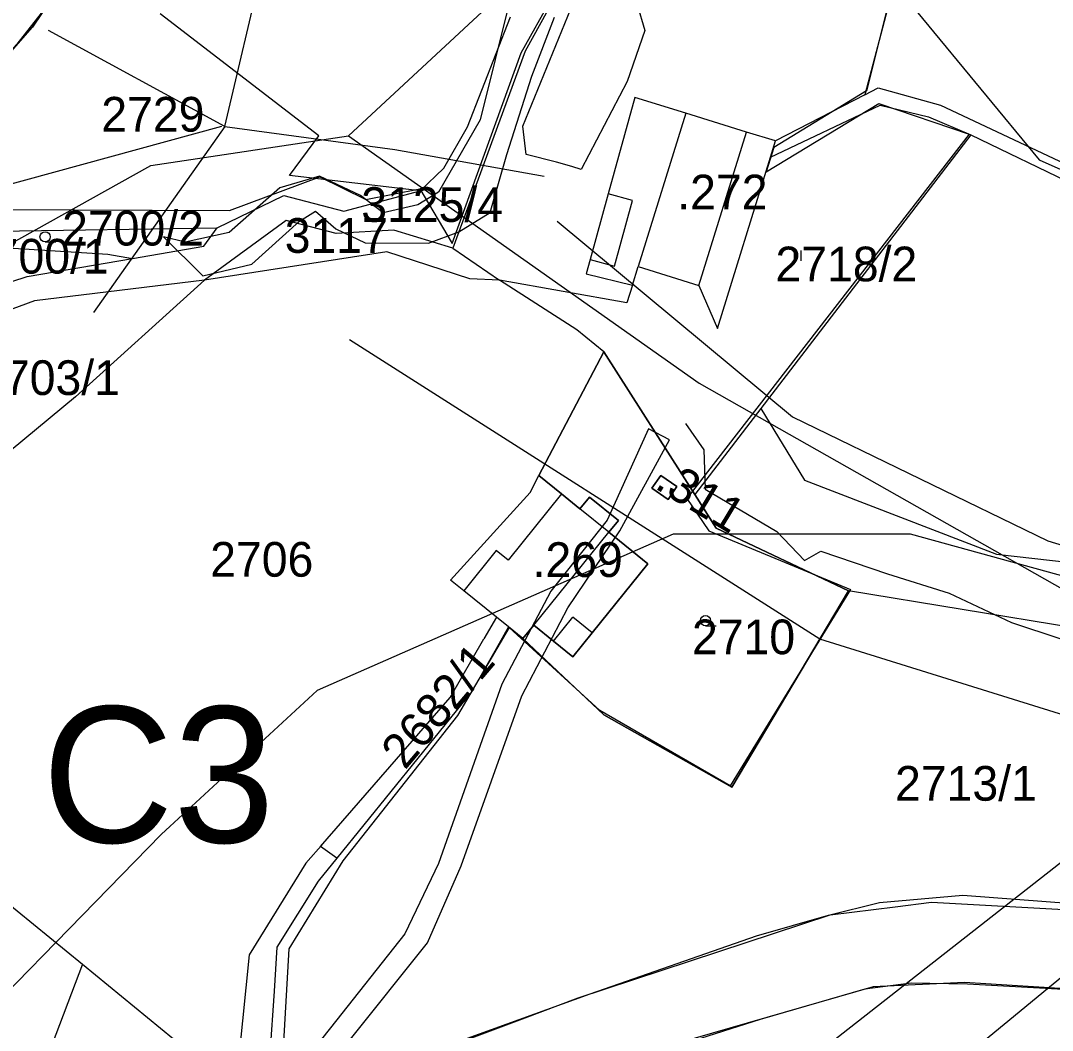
# Model space of a CAD drawing. Extents: x -564810 to -550519, y -1045831 to -1034011.
# Drawn here: x -552426.8 to -552275.1, y -1036269 to -1036120.6 of the extents above; entities that cross this region are included whole.
import ezdxf

# ---------------------------------------------------------------- set-up
doc = ezdxf.new("R2010")
doc.units = 0
for name, color, linetype in [('KN stav', 7, 'Continuous'), ('Obvod KPU', 7, 'Continuous'), ('Odvodněné plochy', 7, 'Continuous'), ('označ pol cest', 7, 'Continuous'), ('Parcelní čísla', 7, 'Continuous'), ('Polní cesty stavající', 7, 'Continuous'), ('STG', 7, 'Continuous'), ('Vedení VN', 7, 'Continuous'), ('vodní toky', 7, 'Continuous'), ('Vrstva 18', 7, 'Continuous'), ('Vrstva 22', 7, 'Continuous'), ('Vrstva 33', 7, 'Continuous'), ('Vrstva 39', 7, 'Continuous'), ('Vrstva 4', 7, 'Continuous'), ('zamokř ploch', 7, 'Continuous')]:
    doc.layers.add(name, color=color, linetype=linetype)

msp = doc.modelspace()

# ---------------------------------------------------------------- linework, layer by layer
at = {"layer": 'KN stav'}
for p, q in [((-552397.46, -1036080.72), (-552425.11, -1036121.49)), ((-552295.16, -1036103.15), (-552302.65, -1036131.45)), ((-552341.89, -1036105.59), (-552352.64, -1036125.03)), ((-552382.96, -1036137.48), (-552406.3, -1036119.56)), ((-552361.09, -1036136.19), (-552354.77, -1036120.01)), ((-552425.11, -1036121.49), (-552447.79, -1036146.11)), ((-552352.64, -1036125.03), (-552363.28, -1036153.98)), ((-552302.65, -1036131.45), (-552300.67, -1036130.43)), ((-552300.67, -1036130.43), (-552291.53, -1036132.98)), ((-552336.5, -1036131.84), (-552340.4, -1036146)), ((-552328.98, -1036134.18), (-552336.5, -1036131.84)), ((-552302.65, -1036131.45), (-552315.78, -1036138.2)), ((-552320.04, -1036136.96), (-552328.98, -1036134.18)), ((-552316.54, -1036140.64), (-552300.39, -1036132.96)), ((-552300.39, -1036132.96), (-552293.28, -1036134.71)), ((-552291.53, -1036132.98), (-552235.54, -1036159.29)), ((-552293.28, -1036134.71), (-552287.04, -1036137.32)), ((-552387.29, -1036143.3), (-552382.96, -1036137.48)), ((-552364.57, -1036142.26), (-552361.09, -1036136.19)), ((-552315.78, -1036138.2), (-552320.04, -1036136.96)), ((-552287.04, -1036137.32), (-552317.96, -1036177.57)), ((-552287.04, -1036137.32), (-552237.04, -1036161.54)), ((-552316.54, -1036140.64), (-552315.78, -1036138.2)), ((-552324.33, -1036165.79), (-552316.54, -1036140.64)), ((-552368.06, -1036145.56), (-552387.29, -1036143.3)), ((-552368.06, -1036145.56), (-552364.57, -1036142.26)), ((-552397.93, -1036151.01), (-552388.1, -1036146.28)), ((-552388.1, -1036146.28), (-552379.31, -1036148.58)), ((-552379.31, -1036148.58), (-552368.06, -1036145.56)), ((-552340.4, -1036146), (-552343.06, -1036155.67)), ((-552431.25, -1036151.53), (-552397.93, -1036151.01)), ((-552399.89, -1036153.71), (-552397.93, -1036151.01)), ((-552387.77, -1036149.95), (-552399.79, -1036158.73)), ((-552380.44, -1036151.87), (-552387.77, -1036149.95)), ((-552371.94, -1036151.38), (-552380.44, -1036151.87)), ((-552363.28, -1036153.98), (-552371.94, -1036151.38)), ((-552435.51, -1036153.55), (-552414.02, -1036154.88)), ((-552410.39, -1036155.51), (-552399.89, -1036153.71)), ((-552363.28, -1036153.98), (-552356.41, -1036158.73)), ((-552425.89, -1036158.17), (-552410.39, -1036155.51)), ((-552414.02, -1036154.88), (-552410.39, -1036155.51)), ((-552372.96, -1036154.52), (-552399.79, -1036158.73)), ((-552360.75, -1036158.49), (-552372.96, -1036154.52)), ((-552343.06, -1036155.67), (-552343.64, -1036157.77)), ((-552336.84, -1036159.44), (-552335.99, -1036156.71)), ((-552335.99, -1036156.71), (-552327.05, -1036159.49)), ((-552431.96, -1036160.17), (-552425.89, -1036158.17)), ((-552399.79, -1036158.73), (-552424.82, -1036161.75)), ((-552399.79, -1036158.73), (-552418.79, -1036175.85)), ((-552356.41, -1036158.73), (-552360.75, -1036158.49)), ((-552337.65, -1036162.06), (-552356.41, -1036158.73)), ((-552345.01, -1036166.01), (-552356.41, -1036158.73)), ((-552343.64, -1036157.77), (-552336.84, -1036159.44)), ((-552336.84, -1036159.44), (-552337.65, -1036162.06)), ((-552327.05, -1036159.49), (-552324.33, -1036165.79)), ((-552424.82, -1036161.75), (-552431.48, -1036164.21)), ((-552341.03, -1036169.22), (-552345.01, -1036166.01)), ((-552350.59, -1036187.42), (-552341.03, -1036169.22)), ((-552341.03, -1036169.22), (-552350.59, -1036187.42)), ((-552327.68, -1036190.21), (-552341.03, -1036169.22)), ((-552341.03, -1036169.22), (-552327.68, -1036190.21)), ((-552418.79, -1036175.85), (-552438.69, -1036192.39)), ((-552317.96, -1036177.57), (-552327.68, -1036190.21)), ((-552317.96, -1036177.57), (-552311.51, -1036188.1)), ((-552351.9, -1036189.91), (-552350.59, -1036187.42)), ((-552350.59, -1036187.42), (-552347.26, -1036190.12)), ((-552347.26, -1036190.12), (-552350.59, -1036187.42)), ((-552332.68, -1036187.42), (-552333.97, -1036189.3)), ((-552333.97, -1036189.3), (-552332.68, -1036187.42)), ((-552330.29, -1036189.06), (-552332.68, -1036187.42)), ((-552332.68, -1036187.42), (-552330.29, -1036189.06)), ((-552331.58, -1036190.94), (-552330.29, -1036189.06)), ((-552330.29, -1036189.06), (-552331.58, -1036190.94)), ((-552311.51, -1036188.1), (-552283.29, -1036198.98)), ((-552363.6, -1036202.79), (-552351.9, -1036189.91)), ((-552347.26, -1036190.12), (-552344.56, -1036192.3)), ((-552344.56, -1036192.3), (-552347.26, -1036190.12)), ((-552344.56, -1036192.3), (-552343.17, -1036190.59)), ((-552343.17, -1036190.59), (-552344.56, -1036192.3)), ((-552343.17, -1036190.59), (-552338.91, -1036194.04)), ((-552338.91, -1036194.04), (-552343.17, -1036190.59)), ((-552333.97, -1036189.3), (-552331.58, -1036190.94)), ((-552331.58, -1036190.94), (-552333.97, -1036189.3)), ((-552327.68, -1036190.21), (-552324.54, -1036195.15)), ((-552324.54, -1036195.15), (-552327.68, -1036190.21)), ((-552338.91, -1036194.04), (-552340.3, -1036195.75)), ((-552340.3, -1036195.75), (-552338.91, -1036194.04)), ((-552324.54, -1036195.15), (-552305.05, -1036204.4)), ((-552305.05, -1036204.4), (-552324.54, -1036195.15)), ((-552340.3, -1036195.75), (-552334.57, -1036200.39)), ((-552334.57, -1036200.39), (-552340.3, -1036195.75)), ((-552283.29, -1036198.98), (-552272.45, -1036200.19)), ((-552334.57, -1036200.39), (-552342.78, -1036210.54)), ((-552342.78, -1036210.54), (-552334.57, -1036200.39)), ((-552361.65, -1036204.37), (-552363.6, -1036202.79)), ((-552356.83, -1036208.27), (-552361.65, -1036204.37)), ((-552305.05, -1036204.4), (-552322.21, -1036233.22)), ((-552322.21, -1036233.22), (-552305.05, -1036204.4)), ((-552269.02, -1036210.3), (-552305.05, -1036204.4)), ((-552356.83, -1036208.27), (-552358.68, -1036211.46)), ((-552355.08, -1036209.69), (-552356.83, -1036208.27)), ((-552355.08, -1036209.69), (-552356.89, -1036212.89)), ((-552352.96, -1036211.4), (-552355.08, -1036209.69)), ((-552351.36, -1036209.43), (-552352.96, -1036211.4)), ((-552352.96, -1036211.4), (-552351.36, -1036209.43)), ((-552348.45, -1036211.78), (-552351.36, -1036209.43)), ((-552351.36, -1036209.43), (-552348.45, -1036211.78)), ((-552363.67, -1036220.06), (-552358.68, -1036211.46)), ((-552341.05, -1036222.63), (-552352.96, -1036211.4)), ((-552352.96, -1036211.4), (-552341.05, -1036222.63)), ((-552345.63, -1036214.06), (-552348.45, -1036211.78)), ((-552348.45, -1036211.78), (-552345.63, -1036214.06)), ((-552342.78, -1036210.54), (-552345.63, -1036214.06)), ((-552345.63, -1036214.06), (-552342.78, -1036210.54)), ((-552356.89, -1036212.89), (-552360.45, -1036219.2)), ((-552360.45, -1036219.2), (-552380.31, -1036243.66)), ((-552382.75, -1036241.98), (-552363.67, -1036220.06)), ((-552322.21, -1036233.22), (-552341.05, -1036222.63)), ((-552341.05, -1036222.63), (-552322.21, -1036233.22)), ((-552380.31, -1036243.66), (-552382.75, -1036241.98)), ((-552380.31, -1036243.66), (-552383.08, -1036247.07)), ((-552383.08, -1036247.07), (-552389.13, -1036256.75)), ((-552429.76, -1036249.45), (-552417.73, -1036259.25)), ((-552307.76, -1036252.02), (-552298.21, -1036250.82)), ((-552298.21, -1036250.82), (-552292.87, -1036250.15)), ((-552292.87, -1036250.15), (-552242.63, -1036252.92)), ((-552344.82, -1036264.22), (-552307.76, -1036252.02)), ((-552389.13, -1036256.75), (-552389.56, -1036263.25)), ((-552417.73, -1036259.25), (-552428.13, -1036286.71)), ((-552417.73, -1036259.25), (-552404.37, -1036270.22)), ((-552389.56, -1036263.25), (-552390.76, -1036281.4)), ((-552301.41, -1036262.6), (-552343.81, -1036274.77)), ((-552287.97, -1036261.97), (-552301.41, -1036262.6)), ((-552266.12, -1036263.35), (-552287.97, -1036261.97)), ((-552353.02, -1036267.28), (-552344.82, -1036264.22)), ((-552390.76, -1036281.4), (-552353.02, -1036267.28))]:
    msp.add_line(p, q, dxfattribs=at)
at = {"layer": 'Obvod KPU'}
for p, q in [((-552353.2, -1036125.31), (-552330.41, -1036084.2)), ((-552295.41, -1036102.94), (-552302.4, -1036130.89)), ((-552363.38, -1036153.34), (-552353.2, -1036125.31)), ((-552302.4, -1036130.89), (-552316.06, -1036139.19)), ((-552317.17, -1036142.76), (-552300.59, -1036132.72)), ((-552300.59, -1036132.72), (-552287.33, -1036137.23)), ((-552287.33, -1036137.23), (-552328.85, -1036190.79)), ((-552316.06, -1036139.19), (-552317.17, -1036142.76)), ((-552396.09, -1036148.48), (-552382.84, -1036143.54)), ((-552382.84, -1036143.54), (-552376.04, -1036146.85)), ((-552376.04, -1036146.85), (-552368.13, -1036145.3)), ((-552368.13, -1036145.3), (-552363.38, -1036153.34)), ((-552431.9, -1036148.29), (-552396.09, -1036148.48)), ((-552328.85, -1036190.79), (-552325.6, -1036195.54)), ((-552325.6, -1036195.54), (-552304.75, -1036204.17)), ((-552304.75, -1036204.17), (-552322.47, -1036233.03)), ((-552354.97, -1036209.79), (-552362.57, -1036222.7)), ((-552341.66, -1036221.97), (-552354.97, -1036209.79)), ((-552322.47, -1036233.03), (-552341.66, -1036221.97)), ((-552362.57, -1036222.7), (-552379.46, -1036244.05)), ((-552379.46, -1036244.05), (-552387.38, -1036256.99)), ((-552387.38, -1036256.99), (-552388.68, -1036279.64))]:
    msp.add_line(p, q, dxfattribs=at)
at = {"layer": 'Odvodněné plochy'}
msp.add_lwpolyline([(-552472.42, -1036175.42), (-552425.11, -1036121.49), (-552397.46, -1036080.72)], dxfattribs=at)
at = {"layer": 'Polní cesty stavající'}
for p, q in [((-552431.52, -1036129.27), (-552418.1, -1036112.21)), ((-552334.49, -1036180.54), (-552340.54, -1036193.98)), ((-552331.41, -1036182.16), (-552334.49, -1036180.54)), ((-552338.7, -1036195.56), (-552331.41, -1036182.16)), ((-552340.54, -1036193.98), (-552348.84, -1036204.41)), ((-552346.33, -1036206.87), (-552338.7, -1036195.56)), ((-552348.84, -1036204.41), (-552356.07, -1036218.1)), ((-552353.13, -1036219.82), (-552346.33, -1036206.87)), ((-552356.07, -1036218.1), (-552365.38, -1036244.47)), ((-552362.01, -1036244.82), (-552353.13, -1036219.82)), ((-552365.38, -1036244.47), (-552370.33, -1036254.79)), ((-552366.99, -1036256.14), (-552362.01, -1036244.82)), ((-552370.33, -1036254.79), (-552381.27, -1036268.6)), ((-552378.51, -1036270.51), (-552366.99, -1036256.14)), ((-552381.27, -1036268.6), (-552390.78, -1036280.68))]:
    msp.add_line(p, q, dxfattribs=at)
at = {"layer": 'STG'}
for points in [[(-552302.75, -1036109.8), (-552277.03, -1036141.04), (-552210.9, -1036170.44), (-552159.46, -1036194.33), (-552104.35, -1036229.24), (-552049.23, -1036221.89), (-551997.79, -1036236.59)], [(-551983.65, -1036332.97), (-552007.53, -1036309.09), (-552044.27, -1036295.3), (-552069.07, -1036358.7), (-552091.12, -1036381.67), (-552122.35, -1036426.69), (-552140.72, -1036452.42), (-552162.77, -1036443.23), (-552167.36, -1036398.21), (-552154.5, -1036338.49), (-552139.8, -1036286.12), (-552154.5, -1036260.39), (-552205.02, -1036223.64), (-552249.11, -1036208.94), (-552295.96, -1036196.07), (-552330.86, -1036196.07), (-552383.22, -1036219.04), (-552406.18, -1036240.18), (-552442.92, -1036277.85)]]:
    msp.add_lwpolyline(points, dxfattribs=at)
at = {"layer": 'Vedení VN'}
for p, q in [((-552396.81, -1036136.11), (-552422.74, -1036122.01)), ((-552397.31, -1036136.11), (-552443.59, -1036148.81)), ((-552396.81, -1036136.11), (-552416.11, -1036163.46))]:
    msp.add_line(p, q, dxfattribs=at)
for points in [[(-552390.69, -1036335.75), (-552182.99, -1036173.21), (-551916.64, -1036001.49), (-551790.75, -1035795.43)], [(-552393.68, -1036360.17), (-552349.55, -1036323.51), (-552259.68, -1036249.59), (-552179.99, -1036184.84), (-552081.56, -1036122.39), (-551986.35, -1036061.29), (-551910.18, -1036013.26), (-551850.19, -1035917.91), (-551788.14, -1035819.06)], [(-552396.81, -1036136.11), (-552385.51, -1036088.23), (-552374.49, -1036041.88), (-552363.46, -1035994.93), (-552350.12, -1035938.33)], [(-552396.81, -1036136.11), (-552371.78, -1036139.49), (-552349.84, -1036143.4)]]:
    msp.add_lwpolyline(points, dxfattribs=at)
at = {"layer": 'vodní toky'}
for p, q in [((-552354.85, -1036117.34), (-552359.25, -1036135.15)), ((-552352.95, -1036136.06), (-552345.92, -1036118.83)), ((-552336.12, -1036118.16), (-552335.04, -1036122.01)), ((-552351.66, -1036128.7), (-552348.29, -1036120.02)), ((-552335.04, -1036122.01), (-552337.6, -1036129.52)), ((-552355.3, -1036140.22), (-552351.66, -1036128.7)), ((-552337.6, -1036129.52), (-552344.37, -1036142.45)), ((-552359.25, -1036135.15), (-552365.38, -1036145.79)), ((-552352.45, -1036140.23), (-552352.95, -1036136.06)), ((-552357.77, -1036148.74), (-552355.3, -1036140.22)), ((-552348.03, -1036141.34), (-552352.45, -1036140.23)), ((-552345.74, -1036142), (-552348.03, -1036141.34)), ((-552344.37, -1036142.45), (-552345.74, -1036142)), ((-552382.85, -1036143.43), (-552388.7, -1036145.12)), ((-552376.82, -1036146.25), (-552382.85, -1036143.43)), ((-552388.7, -1036145.12), (-552396.17, -1036151.72)), ((-552373.52, -1036148.8), (-552376.82, -1036146.25)), ((-552365.38, -1036145.79), (-552368.42, -1036147.62)), ((-552368.42, -1036147.62), (-552373.52, -1036148.8)), ((-552385.84, -1036150.05), (-552383.47, -1036148.54)), ((-552383.47, -1036148.54), (-552380.45, -1036151.18)), ((-552362.36, -1036151.58), (-552357.77, -1036148.74)), ((-552392.85, -1036156.35), (-552385.84, -1036150.05)), ((-552405.8, -1036152.32), (-552400.05, -1036158.08)), ((-552402.63, -1036153.13), (-552405.8, -1036152.32)), ((-552405.8, -1036152.32), (-552400.05, -1036158.08)), ((-552396.17, -1036151.72), (-552402.63, -1036153.13)), ((-552380.45, -1036151.18), (-552376.16, -1036153.21)), ((-552366.83, -1036153.27), (-552362.36, -1036151.58)), ((-552376.16, -1036153.21), (-552366.83, -1036153.27)), ((-552400.05, -1036158.08), (-552392.85, -1036156.35))]:
    msp.add_line(p, q, dxfattribs=at)
msp.add_lwpolyline([(-552329.03, -1036179.8), (-552326.34, -1036183.63), (-552326.12, -1036189.44), (-552315.59, -1036195.68), (-552311.55, -1036199.92), (-552309.11, -1036198.56), (-552299.33, -1036201.88), (-552290.24, -1036204.72), (-552281.09, -1036209.02), (-552259.61, -1036216.15), (-552247.48, -1036219.2), (-552239.65, -1036219.64), (-552235.57, -1036224.59), (-552225.72, -1036227.24), (-552222.78, -1036224.92), (-552216.54, -1036227.26), (-552212.18, -1036226.7), (-552198.93, -1036230.96), (-552194.87, -1036234.52), (-552188.77, -1036235.91), (-552185.72, -1036238.89), (-552171.59, -1036236.59), (-552168.89, -1036237.27)], dxfattribs=at)
at = {"layer": 'Vrstva 18'}
for points in [[(-552347.9, -1036150.05), (-552313.29, -1036178.82), (-552275.73, -1036197.02), (-552244.87, -1036206.41), (-552201.41, -1036221.97), (-552158.18, -1036228.79), (-552099.91, -1036218.98), (-552064.41, -1036237.22), (-552019.61, -1036249.99), (-551999.52, -1036262.77), (-551969.22, -1036306.53), (-551919.21, -1036397.47), (-551869.13, -1036408.41), (-551830.22, -1036426.18)], [(-551853.47, -1036454.62), (-551894.34, -1036442.67), (-551920.44, -1036432.55), (-551937.39, -1036410.68), (-551946.86, -1036393.71), (-551972.63, -1036363.83), (-551991.87, -1036341.51), (-551995.53, -1036316.95), (-552014.17, -1036298.3), (-552051.45, -1036271.67), (-552099.91, -1036237.04), (-552193.9, -1036247.42), (-552309.25, -1036211.49), (-552378.44, -1036167.47)]]:
    msp.add_lwpolyline(points, dxfattribs=at)
at = {"layer": 'Vrstva 33'}
for points in [[(-552487.9, -1036311.48), (-552487.24, -1036258.74), (-552475.61, -1036198.41), (-552465.08, -1036173.84), (-552407.68, -1036141.86), (-552378.62, -1036137.49), (-552358.27, -1036118.6), (-552372.08, -1036090.97), (-552401.14, -1036077.89), (-552462.9, -1036072.08), (-552521.02, -1036078.62), (-552548.63, -1036095.34), (-552579.87, -1036114.96)], [(-552378.62, -1036137.49), (-552327.03, -1036173.84), (-552271.81, -1036205.09), (-552204.25, -1036228.35), (-552188.77, -1036235.91), (-552185.72, -1036238.89), (-552171.59, -1036236.59), (-552168.89, -1036237.27), (-552160.39, -1036243.2), (-552157.72, -1036244.21), (-552154.24, -1036248.3), (-552148.33, -1036254.35)]]:
    msp.add_lwpolyline(points, dxfattribs=at)
at = {"layer": 'Vrstva 39'}
msp.add_line((-552431.52, -1036129.27), (-552418.1, -1036112.21), dxfattribs=at)
for points in [[(-552384.28, -1036278.51), (-552343.06, -1036263.64), (-552318.59, -1036255.12), (-552308.01, -1036252.07), (-552300.5, -1036250.21), (-552288.24, -1036249.11), (-552275.98, -1036250.06), (-552243.04, -1036252.56), (-552230.59, -1036252.05), (-552216.48, -1036251.65), (-552204.06, -1036249.73), (-552193.9, -1036247.42), (-552179.7, -1036242.47), (-552170.06, -1036238.2), (-552167.26, -1036236.79), (-552158.69, -1036231.32), (-552155.01, -1036229.16), (-552142.12, -1036223.5)], [(-552150.88, -1036242.03), (-552157.72, -1036244.21), (-552162.02, -1036246.84), (-552185.51, -1036256.34), (-552198.74, -1036260.09), (-552215.52, -1036263.56), (-552232.6, -1036264.87), (-552272.57, -1036263.04), (-552287.56, -1036262.19), (-552295.82, -1036262.06), (-552302.66, -1036262.96), (-552318.04, -1036267.39), (-552339.94, -1036274.38)]]:
    msp.add_lwpolyline(points, dxfattribs=at)
at = {"layer": 'Vrstva 4'}
for p, q in [((-552328.98, -1036134.18), (-552335.99, -1036156.71)), ((-552327.05, -1036159.49), (-552320.04, -1036136.96)), ((-552336.83, -1036146.98), (-552340.4, -1036146)), ((-552339.49, -1036156.65), (-552336.83, -1036146.98)), ((-552343.06, -1036155.67), (-552339.49, -1036156.65)), ((-552347.26, -1036190.12), (-552355.13, -1036199.85)), ((-552340.3, -1036195.75), (-552344.56, -1036192.3)), ((-552351.36, -1036209.42), (-552340.3, -1036195.75)), ((-552356.87, -1036198.44), (-552361.66, -1036204.36)), ((-552355.13, -1036199.85), (-552356.87, -1036198.44)), ((-552348.45, -1036211.78), (-552345.6, -1036208.26)), ((-552342.78, -1036210.54), (-552345.6, -1036208.26)), ((-552348.45, -1036211.78), (-552351.36, -1036209.42)), ((-552382.3, -1036241.46), (-552384.88, -1036244.42)), ((-552384.88, -1036244.42), (-552393.2, -1036257.87)), ((-552393.2, -1036257.87), (-552395.21, -1036277.73))]:
    msp.add_line(p, q, dxfattribs=at)
at = {"layer": 'zamokř ploch'}
for p, q in [((-552423.24, -1036153.09), (-552421.64, -1036153.09)), ((-552313.07, -1036154.35), (-552313.07, -1036155.85)), ((-552312.07, -1036154.35), (-552312.07, -1036155.85)), ((-552326.1, -1036209.52), (-552324.5, -1036209.52))]:
    msp.add_line(p, q, dxfattribs=at)
for centre in [(-552423.24, -1036152.34), (-552326.1, -1036208.76)]:
    msp.add_circle(centre, 0.75, dxfattribs=at)

# ---------------------------------------------------------------- texts
at = {"layer": 'označ pol cest'}
msp.add_text('C3', height=20, dxfattribs=at).set_placement((-552423.67, -1036241.39))
at = {"layer": 'Parcelní čísla'}
for s, p in [('2729', (-552414.97, -1036136.87)), ('3125/4', (-552376.73, -1036150.14)), ('2700/2', (-552420.74, -1036153.62)), ('3117', (-552387.99, -1036154.69)), ('2700/1', (-552434.74, -1036157.74)), ('2718/2', (-552315.8, -1036158.88)), ('2703/1', (-552433.09, -1036175.59)), ('2706', (-552398.95, -1036202.3)), ('2710', (-552328.08, -1036213.7)), ('2713/1', (-552298.21, -1036235.23))]:
    msp.add_text(s, height=5.1, dxfattribs=at).set_placement(p)
msp.add_text('2682/1', height=5.1, rotation=49.6893, dxfattribs=at).set_placement((-552370.3, -1036230.83))
at = {"layer": 'Vrstva 22'}
for s, p in [('.272', (-552330.25, -1036148.3)), ('.269', (-552351.53, -1036202.34))]:
    msp.add_text(s, height=5.1, dxfattribs=at).set_placement(p)
msp.add_text('.311', height=5.1, rotation=328.7699, dxfattribs=at).set_placement((-552333.75, -1036189.2))

doc.saveas('drawing.dxf')
